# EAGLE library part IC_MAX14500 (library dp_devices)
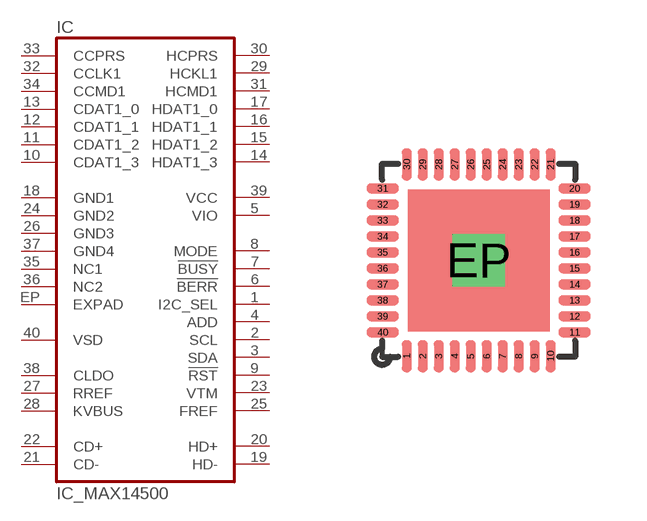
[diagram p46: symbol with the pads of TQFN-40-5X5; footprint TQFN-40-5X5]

Designator prefix IC

## IC_MAX14500-TQFN40-5X5  [TQFN-40-5X5]
1  I2C_SEL
2  SCL
3  SDA
4  ADD
5  VIO
6  !BERR
7  !BUSY
8  MODE
9  !RST
10  CDAT1_3
11  CDAT1_2
12  CDAT1_1
13  CDAT1_0
14  HDAT1_3
15  HDAT1_2
16  HDAT1_1
17  HDAT1_0
18  GND1
19  HD-
20  HD+
21  CD-
22  CD+
23  VTM
24  GND2
25  FREF
26  GND3
27  RREF
28  KVBUS
29  HCKL1
30  HCPRS
31  HCMD1
32  CCLK1
33  CCPRS
34  CCMD1
35  NC1
36  NC2
37  GND4
38  CLDO
39  VCC
40  VSD
EP  EXPAD

## Footprint TQFN-40-5X5 (pad centres in mm)
smd 0.25 x 0.8: 1 -1.8,-2.4; 2 -1.4,-2.4; 3 -1,-2.4; 4 -0.6,-2.4; 5 -0.2,-2.4; 6 0.2,-2.4; 7 0.6,-2.4; 8 1,-2.4; 9 1.4,-2.4; 10 1.8,-2.4; 21 1.8,2.4; 22 1.4,2.4; 23 1,2.4; 24 0.6,2.4; 25 0.2,2.4; 26 -0.2,2.4; 27 -0.6,2.4; 28 -1,2.4; 29 -1.4,2.4; 30 -1.8,2.4
smd 0.8 x 0.25: 11 2.4,-1.8; 12 2.4,-1.4; 13 2.4,-1; 14 2.4,-0.6; 15 2.4,-0.2; 16 2.4,0.2; 17 2.4,0.6; 18 2.4,1; 19 2.4,1.4; 20 2.4,1.8; 31 -2.4,1.8; 32 -2.4,1.4; 33 -2.4,1; 34 -2.4,0.6; 35 -2.4,0.2; 36 -2.4,-0.2; 37 -2.4,-0.6; 38 -2.4,-1; 39 -2.4,-1.4; 40 -2.4,-1.8
drill 0.8 square: EP 0,0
